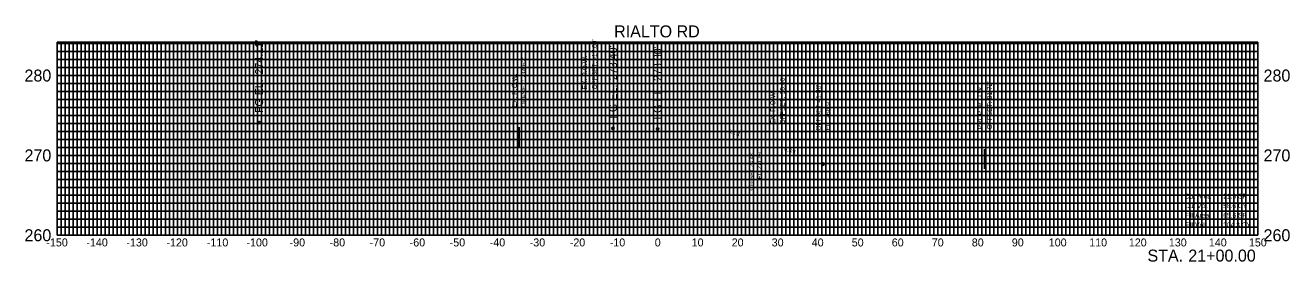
# Model space of a CAD drawing. Extents: x -158 to 158, y 253 to 313.
import ezdxf

# ---------------------------------------------------------------- set-up
doc = ezdxf.new("R2010")
doc.units = 0
for name, color, linetype in [('Default', 7, 'Continuous'), ('DES - ROW - Linework', 7, 'Continuous'), ('DES - SHEET - Light Grid', 7, 'Continuous'), ('DES - SHEET - Linework', 7, 'Continuous'), ('DES - XS - Proposed - Finished Grade Slopes Text', 7, 'Continuous'), ('DES - XS - Proposed - Subgrade Tie Text', 7, 'Continuous'), ('DES - XS - Proposed - Text', 7, 'Continuous'), ('SUR - PROPERTY - ROW Lines', 7, 'Continuous')]:
    doc.layers.add(name, color=color, linetype=linetype)

msp = doc.modelspace()

# ---------------------------------------------------------------- linework, layer by layer
at = {"layer": 'DES - ROW - Linework'}
msp.add_line((81.72, 276.67), (81.72, 281.59), dxfattribs=at)
at = {"layer": 'DES - SHEET - Light Grid'}
for p, q in [((-150, 308), (150, 308)), ((-149, 260), (-149, 308.36)), ((-148, 260), (-148, 308.36)), ((-147, 260), (-147, 308.36)), ((-146, 260), (-146, 308.36)), ((-145, 260), (-145, 308.36)), ((-144, 260), (-144, 308.36)), ((-143, 260), (-143, 308.36)), ((-142, 260), (-142, 308.36)), ((-141, 260), (-141, 308.36)), ((-139, 260), (-139, 308.36)), ((-138, 260), (-138, 308.36)), ((-137, 260), (-137, 308.36)), ((-136, 260), (-136, 308.36)), ((-135, 260), (-135, 308.36)), ((-134, 260), (-134, 308.36)), ((-133, 260), (-133, 308.36)), ((-132, 260), (-132, 308.36)), ((-131, 260), (-131, 308.36)), ((-129, 260), (-129, 308.36)), ((-128, 260), (-128, 308.36)), ((-127, 260), (-127, 308.36)), ((-126, 260), (-126, 308.36)), ((-125, 260), (-125, 308.36)), ((-124, 260), (-124, 308.36)), ((-123, 260), (-123, 308.36)), ((-122, 260), (-122, 308.36)), ((-121, 260), (-121, 308.36)), ((-119, 260), (-119, 308.36)), ((-118, 260), (-118, 308.36)), ((-117, 260), (-117, 308.36)), ((-116, 260), (-116, 308.36)), ((-115, 260), (-115, 308.36)), ((-114, 260), (-114, 308.36)), ((-113, 260), (-113, 308.36)), ((-112, 260), (-112, 308.36)), ((-111, 260), (-111, 308.36)), ((-109, 260), (-109, 308.36)), ((-108, 260), (-108, 308.36)), ((-107, 260), (-107, 308.36)), ((-106, 260), (-106, 308.36)), ((-105, 260), (-105, 308.36)), ((-104, 260), (-104, 308.36)), ((-103, 260), (-103, 308.36)), ((-102, 260), (-102, 308.36)), ((-101, 260), (-101, 308.36)), ((-99, 260), (-99, 308.36)), ((-98, 260), (-98, 308.36)), ((-97, 260), (-97, 308.36)), ((-96, 260), (-96, 308.36)), ((-95, 260), (-95, 308.36)), ((-94, 260), (-94, 308.36)), ((-93, 260), (-93, 308.36)), ((-92, 260), (-92, 308.36)), ((-91, 260), (-91, 308.36)), ((-89, 260), (-89, 308.36)), ((-88, 260), (-88, 308.36)), ((-87, 260), (-87, 308.36)), ((-86, 260), (-86, 308.36)), ((-85, 260), (-85, 308.36)), ((-84, 260), (-84, 308.36)), ((-83, 260), (-83, 308.36)), ((-82, 260), (-82, 308.36)), ((-81, 260), (-81, 308.36)), ((-79, 260), (-79, 308.36)), ((-78, 260), (-78, 308.36)), ((-77, 260), (-77, 308.36)), ((-76, 260), (-76, 308.36)), ((-75, 260), (-75, 308.36)), ((-74, 260), (-74, 308.36)), ((-73, 260), (-73, 308.36)), ((-72, 260), (-72, 308.36)), ((-71, 260), (-71, 308.36)), ((-69, 260), (-69, 308.36)), ((-68, 260), (-68, 308.36)), ((-67, 260), (-67, 308.36)), ((-66, 260), (-66, 308.36)), ((-65, 260), (-65, 308.36)), ((-64, 260), (-64, 308.36)), ((-63, 260), (-63, 308.36)), ((-62, 260), (-62, 308.36)), ((-61, 260), (-61, 308.36)), ((-59, 260), (-59, 308.36)), ((-58, 260), (-58, 308.36)), ((-57, 260), (-57, 308.36)), ((-56, 260), (-56, 308.36)), ((-55, 260), (-55, 308.36)), ((-54, 260), (-54, 308.36)), ((-53, 260), (-53, 308.36)), ((-52, 260), (-52, 308.36)), ((-51, 260), (-51, 308.36)), ((-49, 260), (-49, 308.36)), ((-48, 260), (-48, 308.36)), ((-47, 260), (-47, 308.36)), ((-46, 260), (-46, 308.36)), ((-45, 260), (-45, 308.36)), ((-44, 260), (-44, 308.36)), ((-43, 260), (-43, 308.36)), ((-42, 260), (-42, 308.36)), ((-41, 260), (-41, 308.36)), ((-39, 260), (-39, 308.36)), ((-38, 260), (-38, 308.36)), ((-37, 260), (-37, 308.36)), ((-36, 260), (-36, 308.36)), ((-35, 260), (-35, 308.36)), ((-34, 260), (-34, 308.36)), ((-33, 260), (-33, 308.36)), ((-32, 260), (-32, 308.36)), ((-31, 260), (-31, 308.36)), ((-29, 260), (-29, 308.36)), ((-28, 260), (-28, 308.36)), ((-27, 260), (-27, 308.36)), ((-26, 260), (-26, 308.36)), ((-25, 260), (-25, 308.36)), ((-24, 260), (-24, 308.36)), ((-23, 260), (-23, 308.36)), ((-22, 260), (-22, 308.36)), ((-21, 260), (-21, 308.36)), ((-19, 260), (-19, 308.36)), ((-18, 260), (-18, 308.36)), ((-17, 260), (-17, 308.36)), ((-16, 260), (-16, 308.36)), ((-15, 260), (-15, 308.36)), ((-14, 260), (-14, 308.36)), ((-13, 260), (-13, 308.36)), ((-12, 260), (-12, 308.36)), ((-11, 260), (-11, 308.36)), ((-9, 260), (-9, 308.36)), ((-8, 260), (-8, 308.36)), ((-7, 260), (-7, 308.36)), ((-6, 260), (-6, 308.36)), ((-5, 260), (-5, 308.36)), ((-4, 260), (-4, 308.36)), ((-3, 260), (-3, 308.36)), ((-2, 260), (-2, 308.36)), ((-1, 260), (-1, 308.36)), ((1, 260), (1, 308.36)), ((2, 260), (2, 308.36)), ((3, 260), (3, 308.36)), ((4, 260), (4, 308.36)), ((5, 260), (5, 308.36)), ((6, 260), (6, 308.36)), ((7, 260), (7, 308.36)), ((8, 260), (8, 308.36)), ((9, 260), (9, 308.36)), ((11, 260), (11, 308.36)), ((12, 260), (12, 308.36)), ((13, 260), (13, 308.36)), ((14, 260), (14, 308.36)), ((15, 260), (15, 308.36)), ((16, 260), (16, 308.36)), ((17, 260), (17, 308.36)), ((18, 260), (18, 308.36)), ((19, 260), (19, 308.36)), ((21, 260), (21, 308.36)), ((22, 260), (22, 308.36)), ((23, 260), (23, 308.36)), ((24, 260), (24, 308.36)), ((25, 260), (25, 308.36)), ((26, 260), (26, 308.36)), ((27, 260), (27, 308.36)), ((28, 260), (28, 308.36)), ((29, 260), (29, 308.36)), ((31, 260), (31, 308.36)), ((32, 260), (32, 308.36)), ((33, 260), (33, 308.36)), ((34, 260), (34, 308.36)), ((35, 260), (35, 308.36)), ((36, 260), (36, 308.36)), ((37, 260), (37, 308.36)), ((38, 260), (38, 308.36)), ((39, 260), (39, 308.36)), ((41, 260), (41, 308.36)), ((42, 260), (42, 308.36)), ((43, 260), (43, 308.36)), ((44, 260), (44, 308.36)), ((45, 260), (45, 308.36)), ((46, 260), (46, 308.36)), ((47, 260), (47, 308.36)), ((48, 260), (48, 308.36)), ((49, 260), (49, 308.36)), ((51, 260), (51, 308.36)), ((52, 260), (52, 308.36)), ((53, 260), (53, 308.36)), ((54, 260), (54, 308.36)), ((55, 260), (55, 308.36)), ((56, 260), (56, 308.36)), ((57, 260), (57, 308.36)), ((58, 260), (58, 308.36)), ((59, 260), (59, 308.36)), ((61, 260), (61, 308.36)), ((62, 260), (62, 308.36)), ((63, 260), (63, 308.36)), ((64, 260), (64, 308.36)), ((65, 260), (65, 308.36)), ((66, 260), (66, 308.36)), ((67, 260), (67, 308.36)), ((68, 260), (68, 308.36)), ((69, 260), (69, 308.36)), ((71, 260), (71, 308.36)), ((72, 260), (72, 308.36)), ((73, 260), (73, 308.36)), ((74, 260), (74, 308.36)), ((75, 260), (75, 308.36)), ((76, 260), (76, 308.36)), ((77, 260), (77, 308.36)), ((78, 260), (78, 308.36)), ((79, 260), (79, 308.36)), ((81, 260), (81, 308.36)), ((82, 260), (82, 308.36)), ((83, 260), (83, 308.36)), ((84, 260), (84, 308.36)), ((85, 260), (85, 308.36)), ((86, 260), (86, 308.36)), ((87, 260), (87, 308.36)), ((88, 260), (88, 308.36)), ((89, 260), (89, 308.36)), ((91, 260), (91, 308.36)), ((92, 260), (92, 308.36)), ((93, 260), (93, 308.36)), ((94, 260), (94, 308.36)), ((95, 260), (95, 308.36)), ((96, 260), (96, 308.36)), ((97, 260), (97, 308.36)), ((98, 260), (98, 308.36)), ((99, 260), (99, 308.36)), ((101, 260), (101, 308.36)), ((102, 260), (102, 308.36)), ((103, 260), (103, 308.36)), ((104, 260), (104, 308.36)), ((105, 260), (105, 308.36)), ((106, 260), (106, 308.36)), ((107, 260), (107, 308.36)), ((108, 260), (108, 308.36)), ((109, 260), (109, 308.36)), ((111, 260), (111, 308.36)), ((112, 260), (112, 308.36)), ((113, 260), (113, 308.36)), ((114, 260), (114, 308.36)), ((115, 260), (115, 308.36)), ((116, 260), (116, 308.36)), ((117, 260), (117, 308.36)), ((118, 260), (118, 308.36)), ((119, 260), (119, 308.36)), ((121, 260), (121, 308.36)), ((122, 260), (122, 308.36)), ((123, 260), (123, 308.36)), ((124, 260), (124, 308.36)), ((125, 260), (125, 308.36)), ((126, 260), (126, 308.36)), ((127, 260), (127, 308.36)), ((128, 260), (128, 308.36)), ((129, 260), (129, 308.36)), ((131, 260), (131, 308.36)), ((132, 260), (132, 308.36)), ((133, 260), (133, 308.36)), ((134, 260), (134, 308.36)), ((135, 260), (135, 308.36)), ((136, 260), (136, 308.36)), ((137, 260), (137, 308.36)), ((138, 260), (138, 308.36)), ((139, 260), (139, 308.36)), ((141, 260), (141, 308.36)), ((142, 260), (142, 308.36)), ((143, 260), (143, 308.36)), ((144, 260), (144, 308.36)), ((145, 260), (145, 308.36)), ((146, 260), (146, 308.36)), ((147, 260), (147, 308.36)), ((148, 260), (148, 308.36)), ((149, 260), (149, 308.36)), ((-150, 306), (150, 306)), ((-150, 304), (150, 304)), ((-150, 302), (150, 302)), ((-150, 298), (150, 298)), ((-150, 296), (150, 296)), ((-150, 294), (150, 294)), ((-150, 292), (150, 292)), ((-150, 290), (150, 290)), ((-150, 288), (150, 288)), ((-150, 286), (150, 286)), ((-150, 284), (150, 284)), ((-150, 282), (150, 282)), ((-150, 278), (150, 278)), ((-150, 276), (150, 276)), ((-150, 274), (150, 274)), ((-150, 272), (150, 272)), ((-150, 270), (150, 270)), ((-150, 268), (150, 268)), ((-150, 266), (150, 266)), ((-150, 264), (150, 264)), ((-150, 262), (150, 262))]:
    msp.add_line(p, q, dxfattribs=at)
at = {"layer": 'DES - SHEET - Linework'}
for p, q in [((-150, 308.36), (150, 308.36)), ((-150, 260), (-150, 308.36)), ((-140, 260), (-140, 308.36)), ((-130, 260), (-130, 308.36)), ((-120, 260), (-120, 308.36)), ((-110, 260), (-110, 308.36)), ((-100, 260), (-100, 308.36)), ((-90, 260), (-90, 308.36)), ((-80, 260), (-80, 308.36)), ((-70, 260), (-70, 308.36)), ((-60, 260), (-60, 308.36)), ((-50, 260), (-50, 308.36)), ((-40, 260), (-40, 308.36)), ((-30, 260), (-30, 308.36)), ((-20, 260), (-20, 308.36)), ((-10, 260), (-10, 308.36)), ((0, 260), (0, 308.36)), ((10, 260), (10, 308.36)), ((20, 260), (20, 308.36)), ((30, 260), (30, 308.36)), ((40, 260), (40, 308.36)), ((50, 260), (50, 308.36)), ((60, 260), (60, 308.36)), ((70, 260), (70, 308.36)), ((80, 260), (80, 308.36)), ((90, 260), (90, 308.36)), ((100, 260), (100, 308.36)), ((110, 260), (110, 308.36)), ((120, 260), (120, 308.36)), ((130, 260), (130, 308.36)), ((140, 260), (140, 308.36)), ((150, 260), (150, 308.36)), ((-150, 300), (150, 300)), ((-150, 280), (150, 280)), ((-150, 260), (150, 260))]:
    msp.add_line(p, q, dxfattribs=at)
at = {"layer": 'DES - XS - Proposed - Finished Grade Slopes Text'}
msp.add_circle((41.36, 277.81), 0.3, dxfattribs=at)
at = {"layer": 'DES - XS - Proposed - Text'}
for centre in [(-99.57, 288.21), (-11.16, 286.81), (0, 286.59)]:
    msp.add_circle(centre, 0.3, dxfattribs=at)
at = {"layer": 'SUR - PROPERTY - ROW Lines'}
for p, q in [((-17, 286.67), (-17, 291.59)), ((-34.62, 282.16), (-34.62, 287.08)), ((30, 277.92), (30, 282.84))]:
    msp.add_line(p, q, dxfattribs=at)

# ---------------------------------------------------------------- texts
at = {"layer": 'Default'}
for s, p in [('Cut Area', (131.74, 269.2)), ('21.9 SF', (141.34, 269.2)), ('Cut Vol.        58.6 CY', (131.74, 266.8)), ('Fill Area', (131.74, 264.4)), ('65.6 SF', (141.34, 264.4)), ('Fill Vol.', (131.74, 262)), ('304.3 CY', (141.34, 262))]:
    msp.add_text(s, height=1.2, dxfattribs=at).set_placement(p)
at = {"layer": 'DES - ROW - Linework'}
for s, p in [('PROP. R.O.W.', (81.12, 286.51)), ("81.72'", (83.52, 294.06)), ('OFFSET: ', (83.52, 286.51))]:
    msp.add_text(s, height=1.2, rotation=90, dxfattribs=at).set_placement(p)
at = {"layer": 'DES - XS - Proposed - Finished Grade Slopes Text'}
for s, height, rotation, p in [("41.36'", 1.2, 90, (40.76, 293.26)), ('268.91', 1.2, 90, (43.16, 289.19)), ('OFFSET ', 1.2, 90, (40.76, 286.21)), ('EL. ', 1.2, 90, (43.16, 286.21)), ('6.1:1', 1, 341.9239, (17.58, 285.71)), ('6.3:1', 1, 342.4263, (31.54, 281.22))]:
    msp.add_text(s, height=height, rotation=rotation, dxfattribs=at).set_placement(p)
at = {"layer": 'DES - XS - Proposed - Subgrade Tie Text'}
for s, p in [("24.43'", (23.93, 277.08)), ('271.59', (25.93, 276.56)), ('OFFSET ', (23.93, 271.2)), ('EL. ', (25.93, 274.08))]:
    msp.add_text(s, height=1, rotation=90, dxfattribs=at).set_placement(p)
at = {"layer": 'DES - XS - Proposed - Text'}
for s, height, p in [('RIALTO RD', 3, (-10.87, 309.56)), ('280', 3, (-158.19, 298.5)), ('280', 3, (151.41, 298.5)), ('270', 3, (-158.19, 278.5)), ('270', 3, (151.41, 278.5)), ('260', 3, (-158.19, 258.5)), ('-150', 2, (-152.73, 257.2)), ('-140', 2, (-142.73, 257.2)), ('-130', 2, (-132.73, 257.2)), ('-120', 2, (-122.73, 257.2)), ('-110', 2, (-112.62, 257.2)), ('-100', 2, (-102.73, 257.2)), ('-90', 2, (-91.95, 257.2)), ('-80', 2, (-81.95, 257.2)), ('-70', 2, (-71.95, 257.2)), ('-60', 2, (-61.95, 257.2)), ('-50', 2, (-51.95, 257.2)), ('-40', 2, (-41.95, 257.2)), ('-30', 2, (-31.95, 257.2)), ('-20', 2, (-21.95, 257.2)), ('-10', 2, (-11.95, 257.2)), ('0', 2, (-0.71, 257.2)), ('10', 2, (8.51, 257.2)), ('20', 2, (18.51, 257.2)), ('30', 2, (28.51, 257.2)), ('40', 2, (38.51, 257.2)), ('50', 2, (48.51, 257.2)), ('60', 2, (58.51, 257.2)), ('70', 2, (68.51, 257.2)), ('80', 2, (78.51, 257.2)), ('90', 2, (88.51, 257.2)), ('100', 2, (97.74, 257.2)), ('110', 2, (107.84, 257.2)), ('120', 2, (117.74, 257.2)), ('130', 2, (127.74, 257.2)), ('140', 2, (137.74, 257.2)), ('150', 2, (147.74, 257.2)), ('260', 3, (151.41, 258.5)), (' STA. ', 3, (121.28, 253.4)), ('21+00.00', 3, (132.61, 253.4))]:
    msp.add_text(s, height=height, dxfattribs=at).set_placement(p)
for s, p in [("274.11'", (-98.57, 300.24)), ("273.40'", (-10.16, 298.84)), ("273.30'", (1, 298.62)), ('FG EL. ', (-98.57, 290.61)), ('FG EL. ', (-10.16, 289.21)), ('FG EL. ', (1, 288.99))]:
    msp.add_text(s, height=2, rotation=90, dxfattribs=at).set_placement(p)
at = {"layer": 'SUR - PROPERTY - ROW Lines'}
for s, p in [("-17.00'", (-15.2, 304.06)), ("-34.62'", (-32.82, 299.54)), ('EX. R.O.W. ', (-17.6, 296.51)), ('EX. R.O.W. ', (-35.22, 292)), ('OFFSET: ', (-15.2, 296.51)), ('OFFSET: ', (-32.82, 292)), ("30.00'", (31.8, 295.3)), ('EX. R.O.W. ', (29.4, 287.76)), ('OFFSET: ', (31.8, 287.76))]:
    msp.add_text(s, height=1.2, rotation=90, dxfattribs=at).set_placement(p)

doc.saveas('drawing.dxf')
